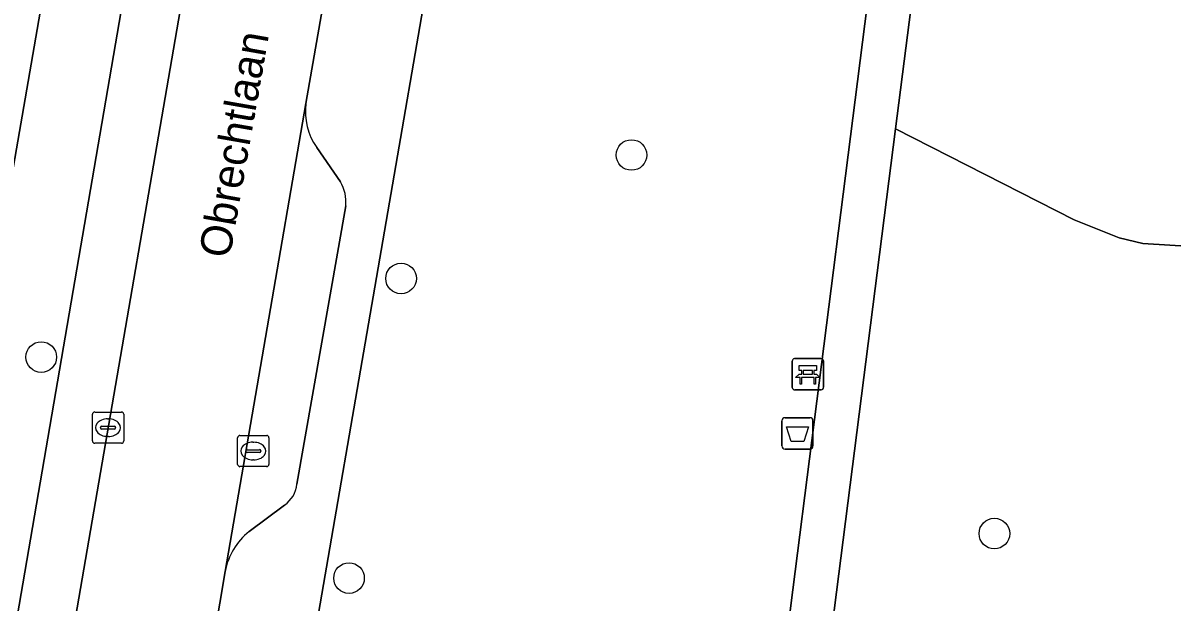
# Model space of a CAD drawing. Extents: x 159817 to 160765, y 380688 to 381638.
# Drawn here: x 160175.41 to 160212.11, y 380921.11 to 380939.61 of the extents above; entities that cross this region are included whole.
import ezdxf

# ---------------------------------------------------------------- set-up
doc = ezdxf.new("R2010")
doc.units = 0
for name, color, linetype in [('IMGEO_Afvalbak', 7, 'Continuous'), ('IMGEO_Bank', 7, 'Continuous'), ('IMGEO_Boom', 7, 'Continuous'), ('IMGEO_Erf', 7, 'Continuous'), ('IMGEO_Groenvoorziening', 7, 'Continuous'), ('IMGEO_Kolk', 7, 'Continuous'), ('IMGEO_Openbare_ruimte_label', 7, 'Continuous'), ('IMGEO_Parkeervlak_open', 7, 'Continuous'), ('IMGEO_Rijbaan_lokaal_open', 7, 'Continuous'), ('IMGEO_Voetpad_halfverhard', 7, 'Continuous'), ('IMGEO_Voetpad_open', 7, 'Continuous')]:
    doc.layers.add(name, color=color, linetype=linetype)

msp = doc.modelspace()

# ---------------------------------------------------------------- linework, layer by layer
at = {"layer": 'IMGEO_Afvalbak'}
for p, q in [((160199.649, 380926.1), (160199.649, 380926.9)), ((160199.649, 380926.9), (160199.649, 380926.1)), ((160199.749, 380927), (160200.539, 380927)), ((160200.539, 380927), (160199.749, 380927)), ((160200.639, 380926.9), (160200.639, 380926.1)), ((160200.639, 380926.1), (160200.639, 380926.9)), ((160200.539, 380926), (160199.749, 380926)), ((160199.749, 380926), (160200.539, 380926))]:
    msp.add_line(p, q, dxfattribs=at)
msp.add_lwpolyline([(160199.792, 380926.714), (160200.496, 380926.714), (160200.347, 380926.244), (160199.941, 380926.244), (160199.792, 380926.714)], dxfattribs=at)
for centre, start, end in [((160199.749, 380926.9), 90, 180), ((160199.749, 380926.9), 90, 180), ((160200.539, 380926.9), 0, 90), ((160200.539, 380926.9), 360, 90), ((160199.749, 380926.1), 180, 270), ((160199.749, 380926.1), 180, 270), ((160200.539, 380926.1), 270, 0), ((160200.539, 380926.1), 270, 0)]:
    msp.add_arc(centre, 0.1, start, end, dxfattribs=at)
at = {"layer": 'IMGEO_Bank'}
for p, q in [((160200.051, 380928.89), (160200.892, 380928.89)), ((160200.892, 380928.89), (160200.051, 380928.89)), ((160199.976, 380927.965), (160199.976, 380928.806)), ((160199.976, 380928.806), (160199.976, 380927.965)), ((160200.976, 380928.815), (160200.976, 380927.974)), ((160200.976, 380927.974), (160200.976, 380928.815)), ((160200.673, 380928.288), (160200.28, 380928.288)), ((160200.285, 380928.396), (160200.285, 380928.502)), ((160200.329, 380928.502), (160200.329, 380928.396)), ((160200.617, 380928.508), (160200.335, 380928.508)), ((160200.335, 380928.39), (160200.617, 380928.39)), ((160200.623, 380928.396), (160200.623, 380928.502)), ((160200.667, 380928.502), (160200.667, 380928.396)), ((160200.901, 380927.89), (160200.06, 380927.89)), ((160200.06, 380927.89), (160200.901, 380927.89))]:
    msp.add_line(p, q, dxfattribs=at)
for points in [[(160200.279, 380928.508), (160200.193, 380928.508), (160200.193, 380928.669), (160200.756, 380928.669), (160200.756, 380928.508), (160200.673, 380928.508)], [(160200.223, 380928.288), (160200.081, 380928.288), (160200.193, 380928.39), (160200.279, 380928.39)], [(160200.273, 380928.281), (160200.273, 380928.074), (160200.23, 380928.074), (160200.23, 380928.281)], [(160200.673, 380928.39), (160200.756, 380928.39), (160200.868, 380928.288), (160200.729, 380928.288)], [(160200.723, 380928.281), (160200.723, 380928.074), (160200.679, 380928.074), (160200.679, 380928.281)]]:
    msp.add_lwpolyline(points, dxfattribs=at)
for centre, radius, start, end in [((160200.054, 380928.812), 0.0779, 92.4484, 184.2845), ((160200.054, 380928.812), 0.0779, 92.4484, 184.2845), ((160200.898, 380928.812), 0.0779, 2.4484, 94.2845), ((160200.898, 380928.812), 0.0779, 2.4484, 94.2845), ((160200.223, 380928.281), 0.00671, 2.8957, 87.1043), ((160200.28, 380928.281), 0.00671, 92.8957, 177.1043), ((160200.278, 380928.501), 0.00671, 2.8957, 87.1043), ((160200.278, 380928.397), 0.00671, 272.8957, 357.1043), ((160200.335, 380928.501), 0.00671, 92.8957, 177.1043), ((160200.335, 380928.397), 0.00671, 182.8957, 267.1043), ((160200.617, 380928.501), 0.00671, 2.8957, 87.1043), ((160200.617, 380928.397), 0.00671, 272.8957, 357.1043), ((160200.674, 380928.501), 0.00671, 92.8957, 177.1043), ((160200.674, 380928.397), 0.00671, 182.8957, 267.1043), ((160200.672, 380928.281), 0.00671, 2.8957, 87.1043), ((160200.729, 380928.281), 0.00671, 92.8957, 177.1043), ((160200.054, 380927.968), 0.0779, 182.4484, 274.2845), ((160200.054, 380927.968), 0.0779, 182.4484, 274.2845), ((160200.898, 380927.968), 0.0779, 272.4484, 4.2845), ((160200.898, 380927.968), 0.0779, 272.4484, 4.2845)]:
    msp.add_arc(centre, radius, start, end, dxfattribs=at)
at = {"layer": 'IMGEO_Boom'}
for centre in [(160194.841, 380935.394), (160187.482, 380931.45), (160175.99, 380928.938), (160206.432, 380923.298), (160185.82, 380921.877)]:
    msp.add_circle(centre, 0.489, dxfattribs=at)
at = {"layer": 'IMGEO_Erf'}
msp.add_lwpolyline([(160175.956, 380939.958), (160171.996, 380940.645), (160170.984, 380934.808), (160169.999, 380929.132), (160169.015, 380923.457), (160168.031, 380917.782), (160167.047, 380912.107), (160166.063, 380906.434), (160165.051, 380900.598), (160169.012, 380899.911)], close=True, dxfattribs=at)
at = {"layer": 'IMGEO_Groenvoorziening'}
for points in [[(160199.765, 380919.663), (160202.992, 380945.042), (160189.482, 380947.418), (160188.75, 380943.396), (160184.645, 380919.573), (160197.526, 380917.93)], [(160216.007, 380942.771), (160204.373, 380944.801), (160203.277, 380936.226), (160208.977, 380933.324), (160210.42, 380932.745), (160211.178, 380932.572), (160212.729, 380932.468)], [(160212.729, 380932.468), (160211.178, 380932.572), (160210.42, 380932.745), (160208.977, 380933.324), (160203.277, 380936.226), (160201.31, 380920.837)]]:
    msp.add_lwpolyline(points, dxfattribs=at)
at = {"layer": 'IMGEO_Kolk'}
for p, q in [((160177.623, 380926.257), (160177.623, 380927.109)), ((160177.698, 380927.183), (160178.55, 380927.183)), ((160178.624, 380927.109), (160178.624, 380926.257)), ((160177.882, 380926.677), (160177.882, 380926.689)), ((160177.925, 380926.726), (160178.323, 380926.726)), ((160178.111, 380926.963), (160178.136, 380926.963)), ((160178.366, 380926.689), (160178.366, 380926.677)), ((160178.32, 380926.64), (160177.922, 380926.64)), ((160178.134, 380926.403), (160178.109, 380926.403)), ((160182.263, 380925.511), (160182.263, 380926.363)), ((160182.338, 380926.437), (160183.19, 380926.437)), ((160183.264, 380926.363), (160183.264, 380925.511)), ((160178.55, 380926.183), (160177.698, 380926.183)), ((160182.522, 380925.931), (160182.522, 380925.943)), ((160182.565, 380925.98), (160182.963, 380925.98)), ((160182.751, 380926.217), (160182.776, 380926.217)), ((160183.006, 380925.943), (160183.006, 380925.931)), ((160182.96, 380925.894), (160182.562, 380925.894)), ((160182.774, 380925.657), (160182.749, 380925.657)), ((160183.19, 380925.437), (160182.338, 380925.437))]:
    msp.add_line(p, q, dxfattribs=at)
for points in [[(160177.623, 380926.257), (160177.623, 380927.109)], [(160177.698, 380927.183), (160178.55, 380927.183)], [(160178.624, 380927.109), (160178.624, 380926.257)], [(160182.263, 380925.511), (160182.263, 380926.363)], [(160182.338, 380926.437), (160183.19, 380926.437)], [(160183.264, 380926.363), (160183.264, 380925.511)], [(160178.55, 380926.183), (160177.698, 380926.183)], [(160183.19, 380925.437), (160182.338, 380925.437)]]:
    msp.add_lwpolyline(points, dxfattribs=at)
for centre, radius, start, end in [((160177.7, 380927.107), 0.0765, 91.552, 178.448), ((160177.7, 380927.107), 0.0765, 91.552, 178.448), ((160178.548, 380927.107), 0.0765, 1.552, 88.448), ((160178.548, 380927.107), 0.0765, 1.552, 88.448), ((160177.922, 380926.686), 0.0403, 85.8775, 175.7526), ((160177.919, 380926.676), 0.0366, 178.938, 274.7102), ((160178.323, 380926.683), 0.043, 264.8664, 352.4533), ((160178.327, 380926.688), 0.0386, 1.7309, 96.639), ((160182.34, 380926.361), 0.0765, 91.552, 178.448), ((160182.34, 380926.361), 0.0765, 91.552, 178.448), ((160183.188, 380926.361), 0.0765, 1.552, 88.448), ((160183.188, 380926.361), 0.0765, 1.552, 88.448), ((160177.7, 380926.259), 0.0765, 181.552, 268.448), ((160177.7, 380926.259), 0.0765, 181.552, 268.448), ((160178.548, 380926.259), 0.0765, 271.552, 358.448), ((160178.548, 380926.259), 0.0765, 271.552, 358.448), ((160182.562, 380925.94), 0.0403, 85.8775, 175.7526), ((160182.967, 380925.942), 0.0386, 1.7309, 96.639), ((160182.559, 380925.93), 0.0366, 178.938, 274.7102), ((160182.963, 380925.937), 0.043, 264.8664, 352.4533), ((160182.34, 380925.513), 0.0765, 181.552, 268.448), ((160182.34, 380925.513), 0.0765, 181.552, 268.448), ((160183.188, 380925.513), 0.0765, 271.552, 358.448), ((160183.188, 380925.513), 0.0765, 271.552, 358.448)]:
    msp.add_arc(centre, radius, start, end, dxfattribs=at)
for centre, major_axis, ratio, start_param, end_param in [((160178.11, 380926.683), (-0.387, 0.002), 0.722429, 4.712389, 7.853982), ((160178.135, 380926.683), (-0.39, 0.002), 0.717154, 1.570796, 4.712389), ((160182.75, 380925.937), (-0.387, 0.002), 0.722429, 4.712389, 7.853982), ((160182.775, 380925.937), (-0.39, 0.002), 0.717154, 1.570796, 4.712389)]:
    msp.add_ellipse(centre, major_axis=major_axis, ratio=ratio, start_param=start_param, end_param=end_param, dxfattribs=at)
at = {"layer": 'IMGEO_Parkeervlak_open'}
for points in [[(160170.586, 380883.008), (160181.868, 380948.362), (160181.971, 380948.956)], [(160179.65, 380946.461), (160171.339, 380898.056), (160170.703, 380894.348), (160169.341, 380886.418)], [(160184.446, 380937.036), (160181.862, 380922.086)], [(160185.549, 380934.541), (160184.792, 380935.637)], [(160184.154, 380924.877), (160185.717, 380933.766)], [(160182.63, 380923.366), (160183.759, 380924.211)]]:
    msp.add_lwpolyline(points, dxfattribs=at)
for centre, radius, start, end in [((160186.337, 380936.762), 1.911, 171.743, 216.0402), ((160184.409, 380933.888), 1.313, 354.6578, 29.8042), ((160183.261, 380924.957), 0.897, 303.7473, 354.909), ((160183.988, 380921.681), 2.165, 128.8671, 169.2054)]:
    msp.add_arc(centre, radius, start, end, dxfattribs=at)
at = {"layer": 'IMGEO_Rijbaan_lokaal_open'}
for points in [[(160186.41, 380947.576), (160181.868, 380948.362), (160170.586, 380883.008), (160169.239, 380875.224), (160169.052, 380874.016), (160173.482, 380873.675), (160173.748, 380874.839), (160177.432, 380896.355), (160181.524, 380920.061)], [(160181.524, 380920.061), (160181.862, 380922.086), (160184.446, 380937.036), (160185.926, 380945.514)]]:
    msp.add_lwpolyline(points, dxfattribs=at)
at = {"layer": 'IMGEO_Voetpad_halfverhard'}
msp.add_lwpolyline([(160200.051, 380910.99), (160201.31, 380920.837), (160203.277, 380936.226), (160204.373, 380944.801), (160202.992, 380945.042), (160199.765, 380919.663)], dxfattribs=at)
at = {"layer": 'IMGEO_Voetpad_open'}
for points in [[(160184.414, 380918.229), (160184.645, 380919.573), (160188.75, 380943.396), (160189.482, 380947.418), (160189.563, 380951.484)], [(160181.971, 380948.956), (160181.991, 380949.073), (160181.361, 380949.186), (160177.667, 380949.826), (160176.356, 380942.265), (160175.956, 380939.958), (160169.012, 380899.911), (160168.783, 380898.588), (160168.272, 380895.643), (160167.783, 380892.824), (160167.19, 380889.373), (160166.636, 380886.17), (160166.264, 380878.576), (160166.279, 380877.485)], [(160169.341, 380886.418), (160170.703, 380894.348), (160171.339, 380898.056), (160179.65, 380946.461)], [(160185.926, 380945.514), (160184.446, 380937.036)], [(160184.792, 380935.637), (160185.549, 380934.541)], [(160185.717, 380933.766), (160184.154, 380924.877)], [(160183.759, 380924.211), (160182.63, 380923.366)], [(160181.862, 380922.086), (160181.524, 380920.061)]]:
    msp.add_lwpolyline(points, dxfattribs=at)
for centre, radius, start, end in [((160186.337, 380936.762), 1.911, 171.743, 216.0402), ((160184.409, 380933.888), 1.313, 354.6578, 29.8042), ((160183.261, 380924.957), 0.897, 303.7473, 354.909), ((160183.988, 380921.681), 2.165, 128.8671, 169.2054)]:
    msp.add_arc(centre, radius, start, end, dxfattribs=at)

# ---------------------------------------------------------------- texts
at = {"layer": 'IMGEO_Openbare_ruimte_label'}
msp.add_text('Obrechtlaan', height=1, rotation=80.0385, dxfattribs=at).set_placement((160182.005, 380932.063))

doc.saveas('drawing.dxf')
